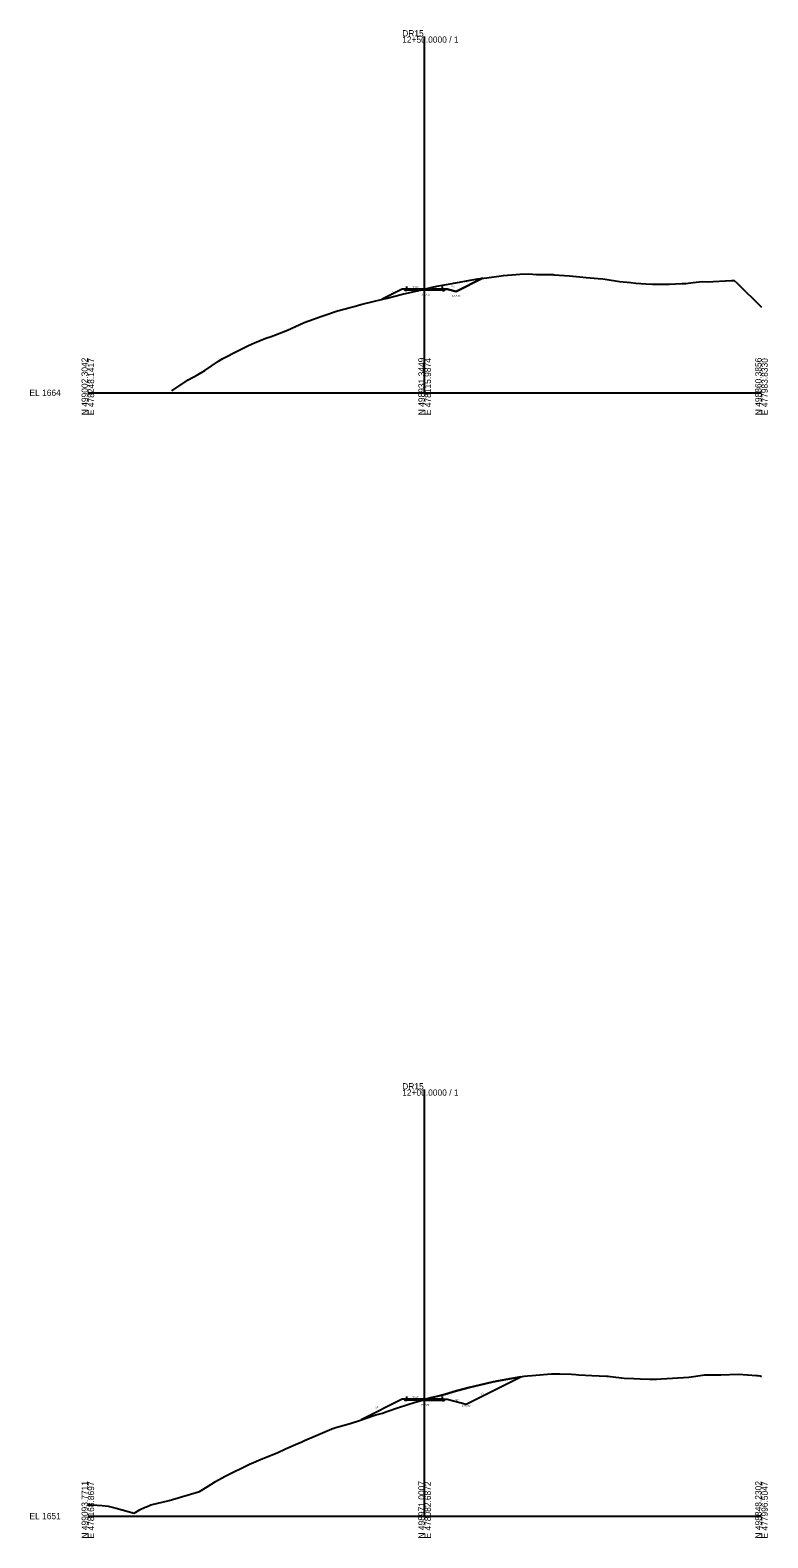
# Model space of a CAD drawing. Extents: x -26 to 303, y -10 to 4126.
# Drawn here: x -26 to 303, y 1990 to 2661 of the extents above; entities that cross this region are included whole.
import ezdxf

# ---------------------------------------------------------------- set-up
doc = ezdxf.new("R2010")
doc.units = 0
for name, color, linetype in [('Exist Cross Section Cell', 7, 'Continuous'), ('Exist XS Center Line Elevation Label', 7, 'Continuous'), ('Exist XS Ground Line', 7, 'Continuous'), ('Prop Road Sect_ Boring - Material (Outline)', 7, 'Continuous'), ('Prop XS Ditch Slope Text', 7, 'Continuous'), ('Prop XS Ditch Standard Text', 7, 'Continuous'), ('Prop XS Earthwork Shape', 7, 'Continuous'), ('Prop XS EOT Tick Mark', 7, 'Continuous'), ('Prop XS Finish Grade', 7, 'Continuous'), ('Prop XS Finish Grade Earthwork', 7, 'Continuous'), ('Prop XS Finish Grade Pavement', 7, 'Continuous'), ('Prop XS Pvmt Edge Slope', 7, 'Continuous'), ('Prop XS SE Text', 7, 'Continuous'), ('Prop XS Side Slope Text', 7, 'Continuous'), ('Prop XS Subgrade Earthwork', 7, 'Continuous')]:
    doc.layers.add(name, color=color, linetype=linetype)

msp = doc.modelspace()

# ---------------------------------------------------------------- linework, layer by layer
at = {"layer": 'Exist Cross Section Cell'}
for p, q in [((150, 2500), (150, 2658.58)), ((0, 2500), (150, 2500)), ((150, 2500), (300, 2500)), ((150, 2000), (150, 2189.89)), ((0, 2000), (150, 2000)), ((150, 2000), (300, 2000))]:
    msp.add_line(p, q, dxfattribs=at)
at = {"layer": 'Exist XS Ground Line'}
for points in [[(37.37, 2500.83), (44.68, 2505.67), (48.77, 2507.99), (52.06, 2509.85), (58.19, 2514), (59.45, 2514.79), (60.12, 2515.23), (66.83, 2518.69), (71.48, 2521.09), (74.22, 2522.25), (79.33, 2524.24), (81.61, 2525.06), (82.83, 2525.54), (88.99, 2527.82), (94.18, 2530.27), (96.38, 2531.2), (100.48, 2532.7), (103.77, 2533.97), (105.53, 2534.54), (111.15, 2536.42), (116.89, 2537.98), (118.54, 2538.39), (121.62, 2539.29), (128.24, 2540.95), (133.31, 2542.12), (139.59, 2543.72), (140.7, 2543.98), (142.76, 2544.48), (148.09, 2545.69), (150, 2546.16), (150.94, 2546.39), (155.47, 2547.36), (162.3, 2548.69), (162.86, 2548.79), (163.91, 2548.97), (170.25, 2550.1), (173.65, 2550.65), (177.63, 2551.2), (185.05, 2552.24), (192.4, 2552.82), (196.35, 2552.86), (199.79, 2552.68), (206.19, 2552.6), (207.18, 2552.57), (207.71, 2552.53), (214.56, 2552.01), (219.06, 2551.63), (221.95, 2551.34), (227.34, 2550.86), (229.34, 2550.63), (230.41, 2550.51), (236.72, 2549.52), (241.76, 2548.99), (244.11, 2548.77), (248.48, 2548.53), (251.5, 2548.36), (253.12, 2548.35), (258.88, 2548.39), (264.47, 2548.57), (266.27, 2548.65), (269.62, 2549), (273.66, 2549.45), (275.82, 2549.41), (286.68, 2549.95), (287.78, 2549.98), (289.14, 2548.76), (300, 2538.01)], [(0, 2005.03), (1.92, 2005.07), (6.45, 2004.65), (9.1, 2004.38), (12.67, 2003.54), (20.63, 2001.25), (23.3, 2002.95), (25.57, 2003.96), (26.15, 2004.12), (28.06, 2004.94), (36.28, 2006.99), (49.74, 2010.91), (53.12, 2012.94), (56.79, 2015.38), (61.19, 2017.75), (72.07, 2023.1), (73.72, 2023.89), (76.08, 2024.84), (80.9, 2026.78), (84.29, 2028.22), (88.08, 2029.91), (93.49, 2032.31), (95.26, 2033.04), (96.51, 2033.6), (102.44, 2036.09), (108.73, 2038.78), (109.62, 2039.1), (110.9, 2039.5), (116.8, 2041.25), (120.95, 2042.59), (123.98, 2043.59), (128.3, 2045), (131.16, 2045.84), (133.17, 2046.5), (138.34, 2048.29), (145.71, 2050.71), (150, 2051.86), (152.7, 2052.58), (157.61, 2053.86), (159.88, 2054.38), (163.12, 2055.38), (167.06, 2056.52), (169.83, 2057.22), (174.24, 2058.28), (180.53, 2059.69), (181.42, 2059.88), (182.05, 2060.01), (188.6, 2061.3), (194.27, 2062.27), (195.78, 2062.44), (197.94, 2062.63), (202.96, 2063.06), (206.49, 2063.26), (210.14, 2063.3), (215.35, 2063.09), (217.32, 2063.01), (218.71, 2062.9), (224.5, 2062.52), (230.93, 2062.26), (231.68, 2062.21), (232.75, 2062.09), (238.86, 2061.36), (243.15, 2061.21), (246.04, 2061.05), (250.16, 2061), (253.22, 2060.89), (255.37, 2061.09), (260.4, 2061.31), (267.59, 2061.79), (274.76, 2062.85), (279.81, 2062.92), (281.94, 2062.93), (289.83, 2063.2), (297.83, 2062.64), (298.34, 2062.6), (299.43, 2062.48), (300, 2062.14)]]:
    msp.add_lwpolyline(points, dxfattribs=at)
at = {"layer": 'Prop Road Sect_ Boring - Material (Outline)'}
for points in [[(142, 2546.21), (141.32, 2545.53), (140.74, 2546.11)], [(158.68, 2545.53), (159.26, 2546.11), (158, 2546.21)], [(142, 2052.16), (140.74, 2052.06), (141.32, 2051.48)], [(158, 2052.16), (159.26, 2052.06), (158.68, 2051.48)]]:
    msp.add_lwpolyline(points, close=True, dxfattribs=at)
at = {"layer": 'Prop XS Earthwork Shape'}
for points in [[(173.65, 2550.65), (175.79, 2550.95), (164, 2545.05), (160, 2546.05), (159.26, 2546.11), (158.68, 2545.53), (158, 2545.54), (150, 2545.7), (147.95, 2545.66), (148.09, 2545.69), (150, 2546.16), (150.94, 2546.39), (155.47, 2547.36), (162.3, 2548.69), (162.86, 2548.79), (163.91, 2548.97), (170.25, 2550.1)], [(142.76, 2544.48), (147.95, 2545.66), (142, 2545.54), (141.32, 2545.53), (140.74, 2546.11), (140, 2546.05), (131.12, 2541.61), (133.31, 2542.12), (139.59, 2543.72), (140.7, 2543.98)], [(158, 2051.49), (158.68, 2051.48), (159.26, 2052.06), (160, 2052), (168.51, 2049.87), (192.81, 2062.02), (188.6, 2061.3), (182.05, 2060.01), (181.42, 2059.88), (180.53, 2059.69), (174.24, 2058.28), (169.83, 2057.22), (167.06, 2056.52), (163.12, 2055.38), (159.88, 2054.38), (157.61, 2053.86), (152.7, 2052.58), (150, 2051.86), (149.16, 2051.63), (150, 2051.65)], [(140.74, 2052.06), (140, 2052), (121.66, 2042.83), (123.98, 2043.59), (128.3, 2045), (131.16, 2045.84), (133.17, 2046.5), (138.34, 2048.29), (145.71, 2050.71), (149.16, 2051.63), (142, 2051.49), (141.32, 2051.48)]]:
    msp.add_lwpolyline(points, close=True, dxfattribs=at)
at = {"layer": 'Prop XS EOT Tick Mark'}
for p, q in [((142, 2546.21), (142, 2547.21)), ((158, 2546.21), (158, 2547.21)), ((142, 2052.16), (142, 2053.16)), ((158, 2052.16), (158, 2053.16))]:
    msp.add_line(p, q, dxfattribs=at)
at = {"layer": 'Prop XS Finish Grade'}
for p, q in [((142, 2546.21), (140.74, 2546.11)), ((158, 2546.21), (159.26, 2546.11)), ((142, 2052.16), (140.74, 2052.06)), ((158, 2052.16), (159.26, 2052.06))]:
    msp.add_line(p, q, dxfattribs=at)
at = {"layer": 'Prop XS Finish Grade Earthwork'}
for p, q in [((164, 2545.05), (175.79, 2550.95)), ((140, 2546.05), (131.12, 2541.61)), ((140.74, 2546.11), (140, 2546.05)), ((159.26, 2546.11), (160, 2546.05)), ((160, 2546.05), (164, 2545.05)), ((168.51, 2049.87), (192.81, 2062.02)), ((140, 2052), (121.66, 2042.83)), ((140.74, 2052.06), (140, 2052)), ((159.26, 2052.06), (160, 2052)), ((160, 2052), (168.51, 2049.87))]:
    msp.add_line(p, q, dxfattribs=at)
at = {"layer": 'Prop XS Finish Grade Pavement'}
for p, q in [((142, 2546.21), (150, 2546.37)), ((150, 2546.37), (158, 2546.21)), ((142, 2052.16), (150, 2052.32)), ((150, 2052.32), (158, 2052.16))]:
    msp.add_line(p, q, dxfattribs=at)
at = {"layer": 'Prop XS Pvmt Edge Slope'}
for p, q in [((142, 2546.21), (141.32, 2545.53)), ((158, 2546.21), (158.68, 2545.53)), ((142, 2052.16), (141.32, 2051.48)), ((158, 2052.16), (158.68, 2051.48))]:
    msp.add_line(p, q, dxfattribs=at)
at = {"layer": 'Prop XS Subgrade Earthwork'}
for p, q in [((141.32, 2545.53), (140.74, 2546.11)), ((142, 2545.54), (141.32, 2545.53)), ((150, 2545.7), (142, 2545.54)), ((158, 2545.54), (150, 2545.7)), ((158, 2545.54), (158.68, 2545.53)), ((158.68, 2545.53), (159.26, 2546.11)), ((141.32, 2051.48), (140.74, 2052.06)), ((142, 2051.49), (141.32, 2051.48)), ((150, 2051.65), (142, 2051.49)), ((158, 2051.49), (150, 2051.65)), ((158, 2051.49), (158.68, 2051.48)), ((158.68, 2051.48), (159.26, 2052.06))]:
    msp.add_line(p, q, dxfattribs=at)

# ---------------------------------------------------------------- texts
at = {"layer": 'Exist Cross Section Cell'}
for s, p in [('12+50.0000 / 1', (140, 2655.78)), ('DR15', (140, 2658.58)), ('EL 1664', (-26, 2498.6)), ('12+00.0000 / 1', (140, 2187.09)), ('DR15', (140, 2189.89)), ('EL 1651', (-26, 1998.6))]:
    msp.add_text(s, height=2.8, dxfattribs=at).set_placement(p)
for s, p in [('N 499002.3042', (0, 2490)), ('E 478248.1417', (2.8, 2490)), ('N 498931.3449', (150, 2490)), ('E 478115.9874', (152.8, 2490)), ('N 498860.3856', (300, 2490)), ('E 477983.8330', (302.8, 2490)), ('N 499093.7711', (0, 1990)), ('E 478168.8697', (2.8, 1990)), ('N 498971.0007', (150, 1990)), ('E 478082.6872', (152.8, 1990)), ('N 498848.2302', (300, 1990)), ('E 477996.5047', (302.8, 1990))]:
    msp.add_text(s, height=2.8, rotation=90, dxfattribs=at).set_placement(p)
at = {"layer": 'Exist XS Center Line Elevation Label'}
for s, p in [('1710.16', (148.61, 2543.41)), ('1702.86', (148.25, 2049.11))]:
    msp.add_text(s, height=0.75, dxfattribs=at).set_placement(p)
at = {"layer": 'Prop XS Ditch Slope Text'}
for p in [(161.79, 2547.15), (163.64, 2051.52)]:
    msp.add_text('4:1', height=0.75, rotation=345.96376, dxfattribs=at).set_placement(p)
at = {"layer": 'Prop XS Ditch Standard Text'}
for s, p in [('1709.05', (162.2, 2542.8)), ('1700.87', (166.72, 2048.69))]:
    msp.add_text(s, height=0.75, dxfattribs=at).set_placement(p)
at = {"layer": 'Prop XS SE Text'}
for rotation, p in [(1.14576, (144.69, 2546.76)), (358.85424, (152.69, 2546.82)), (1.14576, (144.69, 2052.71)), (358.85424, (152.69, 2052.76))]:
    msp.add_text('0.020', height=0.75, rotation=rotation, dxfattribs=at).set_placement(p)
at = {"layer": 'Prop XS Side Slope Text'}
for p in [(168.69, 2549.07), (135, 2544.06), (175.12, 2053.82), (128.23, 2047.79)]:
    msp.add_text('2:1', height=0.75, rotation=26.56505, dxfattribs=at).set_placement(p)

doc.saveas('drawing.dxf')
